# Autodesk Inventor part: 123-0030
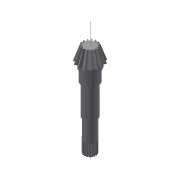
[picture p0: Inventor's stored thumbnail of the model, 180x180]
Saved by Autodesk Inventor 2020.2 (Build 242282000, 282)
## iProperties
+MSCProtocol1+ProtocolID: P00060228091620421
+MSCProtocol2+Protocol: P00060228091620421<@PID>[Version]<@EL>Version=2.2<@EL>[CalcData]<@EL>CalcResult=False<@EL>IsMCW=1<@EL>[Synchronize]<@EL>ChangedVars=<@EL>[Calc]<@EL>Optim=1<@EL>
Manager: www.cadconsulting.pl
Company: Fabian Stasiak CAD Consulting
Shininess: 20.0
Length Units: 11269
Angle Units: 11279
Time Units: 11290
Mass Units: 11283
Length Display Precision: 3
Angle Display Precision: 2
Created: 2001-01
Part Number: 123-0030
Material: Stal 60
Document SubType Name: Modeling
Description: Koło zęb. stożkowe z=15
Project: Przekładnia X51
Designer: F.Stasiak
Density: 7.85 g/cm^3
Appearance: Stal metaliczna (nierdzewna, szczotkowana)
Density: 7.86
Volumn: 5.864026952018771
Area: 31.42094824814569
PropertySet Name: Model Information
Control State: 0
Master: False
Checked Out: False
TAB_mte: 3
TAB_z1: 15
TAB_z2: 51
TAB_betam: 20
TAB_x: 0.1632
TAB_xt: 0
TAB_delta1: 16.3895
TAB_delta2: 73.6105
TAB_IT: 6e26
TAB_fpt1: ±0.01
TAB_fpt2: ±0.011
TAB_tfa: 0
TAB_sk1: 4.305
TAB_sk2: 3.699
TAB_ECs1: -0.03
TAB_ECd1: -0.08
TAB_ECs2: -0.04
TAB_ECd2: -0.1
TAB_hk1: 2.706
TAB_hk2: 1.837
TAB_omega: 90
TAB_de1: 45
TAB_de2: 153
TAB_le: 79.74
TAB_deltaf1: 14.1558
TAB_deltaf2: 70.6745
TAB_alfat: 20
+MSCFeatProtocols1+FeatNameP00060309103952671: SPLINE2A1
+MSCFeatProtocols2+ProtocolIDP00060309103952671: P00060309103952671
+MSCFeatProtocols3+ProtocolP00060309103952671: P00060309103952671<@PID>[Version]<@EL>Version=2.2<@EL>[Files]<@EL>DataFile=SpiData|Evol<@EL>[Synchronize]<@EL>ChangedVars=<@EL>[Calc]<@EL>CalcName=SPLINE2<@EL>O
Author: F.Stasiak
Subject: Zbiór ćwiczeń. Autodesk Inventor 2020. Kurs podstawowy
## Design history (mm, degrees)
sketch "Base Body Sketch"
  geometry: L1 (15.54, 1.12)-(11.733, 0); L2 (15.54, 1.12)-(25.848, -28.995); L3 (25.848, -28.995)-(19.516, -30.858); L4 (-2.585, 0)-(33.602, 0) reference; L5 (11.733, 0)-(0, 0); L6 (0, -30.858)-(19.516, -30.858); L7 (0, 0)-(0, -30.858); L8 (15.54, 1.12)-(0, 46.52); L9 (0, 0)-(0, 46.52); L10 (0, -38.596)-(0, 69.733) reference; L11 (0, 46.52)-(22.5, -29.98); L12 (0, 46.52)-(11.733, 0); L13 (11.733, 0)-(19.516, -30.858)
  constraints: 22 end point, 3 collinear, 2 parallel, 2 perpendicular, 2 point on line
  dimensions: "d33" = 31.8 distance between parallel lines of L3 L1 (= prf_b); "d34" = 51.696 diameter of L2.end L7 (= msp_dae); "d35" = 39.032 diameter of L3.end L7 (= msp_dfe); "d37" = 79.74 distance from line of L3 L8.end (= prf_le); "d41" = 16.3895 deg angle of L9 L11 (= msp_delta); "d59" = 11.7331 distance of L5.end L1.end (derived)
revolve "Base Body" sketch "Base Body Sketch" stored, may be unused: angle "d10" = 360 deg
node "Tooth Plane"
workpoint "Work Point"
sketch "Sketch2"
  geometry: L1 (5.15, 4.81)-(-5.15, 4.81); L2 (0, -5.75)-(5.15, 4.81); L3 (-5.15, 4.81)-(0, -5.75); L4 (0, 2.5)-(0, -3) reference; L5 (0, 2.5)-(0, -3) reference; L6 (0, 2.5)-(0, -3) reference; L7 (0, -51.448)-(0, 23.35) reference; L8 (0, -51.448)-(0, 23.35) reference; L9 (31.018, -13.126)-(-41.357, -13.126) reference; A1 r 6.536 centre (0, 0.786) between (-5.15, 4.81) and (0, -5.75); 1 further point; 1 other entity
  constraints: 6 end point, 3 point on circle, 2 point on line, 1 centre point, 1 horizontal, 1 vertical alignment, 1 other
  dimensions: "d42" = 52 deg angle of L3 L2 (= msp_a2); "d43" = 10.56 distance from line of L2.start L1 (= 1.6 x msp_he); "d54" = 15.55768 distance of L2.start point (0, -21.308) (= msp_y)
extrude "Tooth" cut sketch "Sketch2" distance "d18" = 32.436 (= 1.02 x prf_b); taper "d19" = -1.88111 deg (= msp_a1)
pattern_circular "Tooth Pattern" dims angle "d22" = 360 deg
revolve "Fix Body" stored, may be unused: angle "d23" = 360 deg
node "Gear Axis"
node "Intersection"
node "Mesh Plane"
sketch "Szkic9"
  geometry: A1 r 19.516 centre (0, 0) between (9.079, 17.275) and (6.763, 18.307) reference; A2 r 19.516 centre (0, 0) between (6.763, 18.307) and (1.268, 19.475) reference; A3 r 19.516 centre (0, 0) between (1.268, 19.475) and (-1.268, 19.475) reference; A4 r 19.516 centre (0, 0) between (-1.268, 19.475) and (-6.763, 18.307) reference; A5 r 19.516 centre (0, 0) between (-6.763, 18.307) and (-9.079, 17.275) reference; A6 r 19.516 centre (0, 0) between (-9.079, 17.275) and (-13.624, 13.973) reference; A7 r 19.516 centre (0, 0) between (-13.624, 13.973) and (-15.321, 12.089) reference; A8 r 19.516 centre (0, 0) between (-15.321, 12.089) and (-18.13, 7.224) reference; A9 r 19.516 centre (0, 0) between (-18.13, 7.224) and (-18.913, 4.812) reference; A10 r 19.516 centre (0, 0) between (-18.913, 4.812) and (-19.501, -0.775) reference; A11 r 19.516 centre (0, 0) between (-19.501, -0.775) and (-19.236, -3.297) reference; A12 r 19.516 centre (0, 0) between (-19.236, -3.297) and (-17.5, -8.639) reference; A13 r 19.516 centre (0, 0) between (-17.5, -8.639) and (-16.232, -10.835) reference; A14 r 19.516 centre (0, 0) between (-16.232, -10.835) and (-12.473, -15.01) reference; A15 r 19.516 centre (0, 0) between (-12.473, -15.01) and (-10.421, -16.501) reference; A16 r 19.516 centre (0, 0) between (-10.421, -16.501) and (-5.289, -18.786) reference; A17 r 19.516 centre (0, 0) between (-5.289, -18.786) and (-2.809, -19.313) reference; A18 r 19.516 centre (0, 0) between (-2.809, -19.313) and (2.809, -19.313) reference; A19 r 19.516 centre (0, 0) between (2.809, -19.313) and (5.289, -18.786) reference; A20 r 19.516 centre (0, 0) between (5.289, -18.786) and (10.421, -16.501) reference; A21 r 19.516 centre (0, 0) between (10.421, -16.501) and (12.473, -15.01) reference; A22 r 19.516 centre (0, 0) between (12.473, -15.01) and (16.232, -10.835) reference; A23 r 19.516 centre (0, 0) between (16.232, -10.835) and (17.5, -8.639) reference; A24 r 19.516 centre (0, 0) between (17.5, -8.639) and (19.236, -3.297) reference; A25 r 19.516 centre (0, 0) between (19.236, -3.297) and (19.501, -0.775) reference; A26 r 19.516 centre (0, 0) between (19.501, -0.775) and (18.913, 4.812) reference; A27 r 19.516 centre (0, 0) between (18.913, 4.812) and (18.13, 7.224) reference; A28 r 19.516 centre (0, 0) between (18.13, 7.224) and (15.321, 12.089) reference; A29 r 19.516 centre (0, 0) between (15.321, 12.089) and (13.624, 13.973) reference; A30 r 19.516 centre (0, 0) between (13.624, 13.973) and (9.079, 17.275) reference
extrude "Wyciągnięcie proste2" join sketch "Szkic9" distance "d77" = 10; taper "d78" = 0 deg
sketch "Szkic10"
  geometry: L1 (19.516, -40.858)-(-19.516, -40.858) reference; L2 (0, -214.658)-(0, 6.542) reference; L3 (-17.5, -40.858)-(-17.5, -65.858); L4 (-17.5, -65.858)-(-14.5, -65.858); L5 (-12.5, -198.858)-(0, -198.858); L6 (0, -40.858)-(-17.5, -40.858); L7 (0, -198.858)-(0, -40.858); L8 (-14.5, -65.858)-(-14.5, -130.858); L9 (-14.5, -130.858)-(-12.5, -130.858); L10 (-12.5, -130.858)-(-12.5, -198.858)
  constraints: 16 end point, 3 parallel, 3 perpendicular, 3 point on line, 2 collinear, 1 midpoint
  dimensions: "d79" = 25 distance of L3.start L3.end; "d83" = 25 diameter of L10 L2; "d84" = 35 diameter of L3 L2; "d85" = 29 diameter of L8 L2; "d86" = 158 distance between parallel lines of L6 L5; "d88" = 68 distance of L9.end L5.start
revolve "Obrót4" sketch "Szkic10" stored, may be unused: angle "d87" = 90 deg
node "Oś konstrukcyjna7"
node "Punkt konstrukcyjny4"
sketch "Szkic11"
  geometry: L1 (0, 0.051)-(0, 12.54); L2 (0, 0.051)-(1.932, 11.007); A1 r 4.835 centre (-3.042, 9.298) between (1.452, 11.081) and (0.545, 12.54); A2 r 11.125 centre (0, 0.051) between (1.452, 11.081) and (1.932, 11.007); A3 r 11.125 centre (0, 0.051) between (1.932, 11.007) and (1.452, 11.081); A4 r 12.5 centre (0, 0.051) between (2.171, 12.362) and (0.545, 12.54); A5 r 11.125 centre (0, 0.051) between (2.408, 10.913) and (1.932, 11.007); A6 r 4.835 centre (6.021, 7.7) between (3.759, 11.973) and (2.408, 10.913); A7 r 12.5 centre (0, 0.051) between (3.759, 11.973) and (2.171, 12.362); 1 further point
  constraints: 14 point on circle, 7 centre point, 5 coincident, 5 end point, 3 symmetric about line, 1 horizontal alignment, 1 point on line, 1 vertical, 3 other
  dimensions: "d89" = 4.83467 radius of A1 (= d90); "d115" = 22.25 diameter of A2 (= d101); "d114" = 3.04162 distance from line of A1.centre L1 (= d111); "d113" = 9.24642 vertical distance of L1.start A1.centre (= d91); "d116" = 10 deg angle of L2 L1 (computed from d96); "d117" = 25 diameter of A4 (= d99)
feature "SPLINE2A1" sketch "Szkic11"
node "Bryła1"
node "Korpusy bryłowe"
node "Korpusy powierzchniowe"
sketch "Sketch7"
  geometry: L1 (-12, 0)-(16, 0) reference; L2 (0, -12)-(0, 16) reference; 2 further points
  constraints: 1 coincident
hole "Hole" sketch "Sketch7" diameter "d47" = 9.758 (= hole); stored, may be unused: countersink angle "d51" = 60 deg, drill point angle "d53" = 118 deg; dims "d48" = 6, "d49" = 4, "d50" = 2, "d52" = 8
sketch "Sketch3"
  geometry: L1 (-11.733, 0)-(0, 0); L2 (-19.516, -30.858)-(-11.733, 0); L3 (0, -30.858)-(-19.516, -30.858); L4 (0, 0)-(0, -30.858); L5 (-19.516, -30.858)-(19.516, -30.858) reference; L6 (-11.733, 0)-(11.733, 0) reference; L7 (0, -33.944)-(0, 9.257) reference; 1 further point
  constraints: 8 end point, 2 horizontal, 2 point on line, 1 vertical
  dimensions: "d57" = 39.032 diameter of L2.start L7 (= msp_dfe); "d58" = 0 distance between parallel lines of L7 L4; "d60" = 11.7331 distance of L1.start L1.end (= d59)
node "Pętla rzutowana2"
other parameters: "prf_le" = 79.74 [user parameter; used in 3 equation terms], "prf_delta1" = 2.86051 [user parameter; used in 1 equation term], "prf_he1" = 6.6 [user parameter; used in 1 equation term], "prf_dfe1" = 39.032 [user parameter; used in 1 equation term], "prf_dae1" = 51.696 [user parameter; used in 1 equation term], "prf_de1" = 45 [user parameter; used in 1 equation term], "prf_b" = 31.8 [user parameter; used in 2 equation terms], "prf_omega" = 90 deg [user parameter; used in 1 equation term], "msp_delta" = 16.3895 deg (= prf_delta1) [user parameter; used in 3 equation terms], "msp_he" = 6.6 (= prf_he1) [user parameter; used in 2 equation terms], "msp_dfe" = 39.032 (= prf_dfe1) [user parameter; used in 3 equation terms], "msp_dae" = 51.696 (= prf_dae1) [user parameter; used in 2 equation terms], "msp_de" = 45 (= prf_de1) [user parameter; used in 1 equation term], "hole" = 9.758 (= 0.25 x msp_dfe) [user parameter; used in 1 equation term], "msp_y" = 15.55768 (computed from msp_delta, msp_dae, msp_he) [user parameter; used in 1 equation term], "msp_a1" = -1.88111 deg (computed from msp_de, msp_z, prf_le) [user parameter; used in 1 equation term], "msp_a2" = 52 deg (computed from msp_z) [user parameter; used in 1 equation term], "msp_dist" = 76.49982 (computed from prf_le, msp_delta) [user parameter], "d0" = 3.62545 (derived), "d4" = 38.7702 (derived), "d6" = 32.175 (derived), "d8" = 21.89 (derived), "d12" = 0 (derived), "d14" = -13.24579 (derived), "d16" = 9.83731 (derived), "d40" = 19.14 (derived), "d62" = 0, "d63" = 90 deg (= prf_omega), "d64" = 2.94118 (computed from prf_z1, prf_z2), "d65" = 0, "d66" = 0, "d90" = 4.83467 (computed from d112, d111, d91) [user parameter; used in 1 equation term], "d91" = 9.24642 (computed from d110, d109, d92) [user parameter; used in 4 equation terms], "d92" = 6.44 (computed from d107, d106, d104, d93) [user parameter; used in 1 equation term], "d93" = -19.56689 (computed from d105, d104, d94) [user parameter; used in 2 equation terms], "d94" = -0.41592 (= d103 - d95) [user parameter; used in 2 equation terms], "d95" = -1.03618 (computed from d98, d96) [user parameter; used in 5 equation terms], "d98" = 11.88889 (= 0.222222 x d101 + 0.277778 x d99) [user parameter; used in 2 equation terms], "d99" = 25 [user parameter; used in 5 equation terms], "d101" = 22.25 [user parameter; used in 5 equation terms], "d103" = -1.4521 (computed from d101, d96) [user parameter; used in 2 equation terms], "d104" = 11.84365 (computed from d98, d96) [user parameter; used in 5 equation terms], "d105" = 11.02982 (computed from d101, d96) [user parameter; used in 2 equation terms], "d106" = 12.4881 (computed from d99, d96) [user parameter; used in 2 equation terms], "d107" = -0.49094 (= d95 - d108) [user parameter; used in 2 equation terms], "d108" = -0.54524 (computed from d99, d96) [user parameter; used in 2 equation terms], "d109" = 21.13399 (computed from d105, d103, d95, d104, d94) [user parameter; used in 2 equation terms], "d110" = 15.17929 (computed from d104, d95, d108, d106, d107) [user parameter; used in 1 equation term], "d111" = 3.04162 (computed from d109, d91, d93) [user parameter; used in 3 equation terms], "d112" = 7.13737 (computed from d95, d111, d104, d91) [user parameter; used in 1 equation term]
